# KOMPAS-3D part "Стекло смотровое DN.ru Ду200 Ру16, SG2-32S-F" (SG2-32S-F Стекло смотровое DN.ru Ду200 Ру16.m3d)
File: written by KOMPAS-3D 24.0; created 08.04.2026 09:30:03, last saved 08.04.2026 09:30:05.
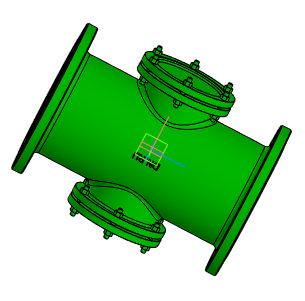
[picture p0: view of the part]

Document properties: Автор: Main; Полное имя файла: D:\DN.ru Аутсерс\Стекло смотровое DN.ru\SG2-32S-F Стекло смотровое DN.ru Ду200 Ру16\SG2-32S-F Стекло смотровое DN.ru Ду200 Ру16.m3d

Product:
- Body: Тело 1  | qty 1
    Масса: 65.830714
- Part/product: Стекло смотровое DN.ru Ду200 Ру16  | designation SG2-32S-F
    Масса: 55
    Раздел спецификации: Прочие изделия
    Примечание: D500-00114

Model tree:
1. Операция без истории:1

Expressions: SG2-32S-F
